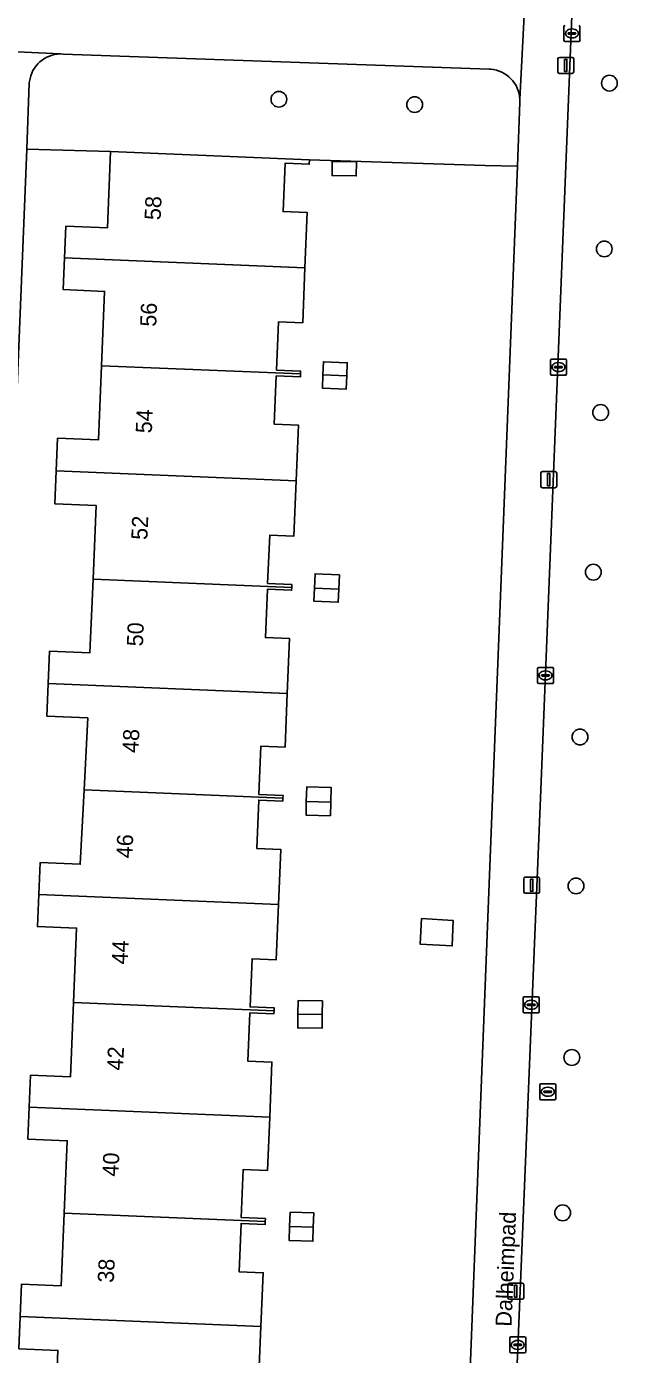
# Model space of a CAD drawing. Extents: x 160786 to 161429, y 386828 to 387485.
# Drawn here: x 161092.1 to 161129.1, y 386964.9 to 387047.4 of the extents above; entities that cross this region are included whole.
import ezdxf

# ---------------------------------------------------------------- set-up
doc = ezdxf.new("R2010")
doc.units = 0
for name, color, linetype in [('IMGEO_Boom', 7, 'Continuous'), ('IMGEO_Erf', 7, 'Continuous'), ('IMGEO_Groenvoorziening', 7, 'Continuous'), ('IMGEO_Kolk', 7, 'Continuous'), ('IMGEO_Lichtmast', 7, 'Continuous'), ('IMGEO_Openbare_ruimte_label', 7, 'Continuous'), ('IMGEO_Pand', 7, 'Continuous'), ('IMGEO_Pand_nummerreeks', 7, 'Continuous'), ('IMGEO_Rioolput', 7, 'Continuous'), ('IMGEO_Voetpad_open', 7, 'Continuous')]:
    doc.layers.add(name, color=color, linetype=linetype)

msp = doc.modelspace()

# ---------------------------------------------------------------- linework, layer by layer
at = {"layer": 'IMGEO_Boom'}
for centre in [(161128.309, 387043.866), (161107.785, 387042.864), (161116.214, 387042.533), (161127.99, 387033.572), (161127.766, 387023.417), (161127.313, 387013.503), (161126.485, 387003.27), (161126.234, 386994.026), (161125.975, 386983.377), (161125.408, 386973.732)]:
    msp.add_circle(centre, 0.489, dxfattribs=at)
at = {"layer": 'IMGEO_Erf'}
for points in [[(161091.805, 386969.307), (161094.274, 386969.205), (161094.46, 386973.708), (161094.645, 386978.211), (161092.204, 386978.311), (161092.285, 386980.29), (161092.367, 386982.27), (161094.843, 386982.168), (161095.033, 386986.787), (161095.224, 386991.406), (161092.789, 386991.506), (161092.87, 386993.49), (161092.952, 386995.477), (161095.453, 386995.374), (161095.688, 386999.985), (161095.916, 387004.462), (161093.376, 387004.569), (161093.461, 387006.59), (161093.545, 387008.608), (161096.05, 387008.502), (161096.242, 387013.075), (161096.435, 387017.648), (161093.867, 387017.756), (161093.952, 387019.788), (161094.037, 387021.819), (161096.573, 387021.712), (161096.767, 387026.322), (161096.961, 387030.937), (161094.394, 387031.045), (161094.477, 387033.018), (161094.559, 387034.989), (161097.135, 387034.881), (161097.334, 387039.615), (161092.128, 387039.776), (161090.524, 387000)], [(161119.475, 386959.244), (161121.076, 387000), (161122.596, 387038.706), (161120.603, 387038.743), (161109.681, 387039.096), (161109.67, 387038.826), (161108.171, 387038.889), (161108.045, 387035.892), (161109.545, 387035.829), (161109.403, 387032.398), (161109.261, 387028.986), (161107.762, 387029.048), (161107.637, 387026.051), (161109.136, 387025.989), (161109.129, 387025.809), (161109.122, 387025.629), (161107.623, 387025.691), (161107.498, 387022.694), (161108.997, 387022.632), (161108.853, 387019.169), (161108.711, 387015.74), (161107.212, 387015.802), (161107.087, 387012.805), (161108.586, 387012.743), (161108.579, 387012.563), (161108.572, 387012.383), (161107.073, 387012.445), (161106.948, 387009.448), (161108.447, 387009.386), (161108.305, 387005.973), (161108.167, 387002.648), (161106.668, 387002.71), (161106.543, 386999.713), (161108.042, 386999.651), (161108.035, 386999.471), (161108.027, 386999.291), (161106.529, 386999.353), (161106.404, 386996.356), (161107.902, 386996.294), (161107.76, 386992.871), (161107.618, 386989.446), (161106.119, 386989.508), (161105.994, 386986.511), (161107.493, 386986.449), (161107.486, 386986.269), (161107.479, 386986.089), (161105.98, 386986.151), (161105.855, 386983.154), (161107.354, 386983.092), (161107.212, 386979.67), (161107.074, 386976.367), (161105.575, 386976.429), (161105.451, 386973.432), (161106.949, 386973.37), (161106.942, 386973.19), (161106.935, 386973.01), (161105.436, 386973.072), (161105.311, 386970.075), (161106.811, 386970.013), (161106.672, 386966.677), (161106.528, 386963.209)], [(161093.874, 386960.552), (161094.065, 386965.19), (161091.639, 386965.29)]]:
    msp.add_lwpolyline(points, dxfattribs=at)
for points in [[(161111.099, 387038.992), (161112.604, 387038.973), (161112.593, 387038.108), (161111.088, 387038.127)], [(161110.484, 387024.931), (161110.518, 387025.751), (161110.552, 387026.573), (161112.034, 387026.511), (161112, 387025.69), (161111.966, 387024.87)], [(161109.952, 387011.708), (161109.99, 387012.504), (161110.032, 387013.404), (161111.546, 387013.333), (161111.504, 387012.442), (161111.466, 387011.636)], [(161109.488, 386999.258), (161109.51, 387000.174), (161111.03, 387000.138), (161111.008, 386999.221), (161110.988, 386998.385), (161109.468, 386998.421)], [(161116.547, 386990.415), (161116.641, 386992.002), (161118.605, 386991.889), (161118.545, 386990.303)], [(161108.955, 386985.211), (161108.964, 386986.061), (161108.972, 386986.905), (161110.485, 386986.891), (161110.477, 386986.047), (161110.469, 386985.196)], [(161108.419, 386972.018), (161108.446, 386972.884), (161108.474, 386973.77), (161109.948, 386973.724), (161109.92, 386972.837), (161109.893, 386971.972)]]:
    msp.add_lwpolyline(points, close=True, dxfattribs=at)
at = {"layer": 'IMGEO_Groenvoorziening'}
msp.add_lwpolyline([(161126.838, 387069.748), (161124.044, 387000), (161122.553, 386963.852)], dxfattribs=at)
msp.add_lwpolyline([(161122.596, 387038.706), (161122.753, 387042.692), (161122.751, 387042.869), (161122.734, 387043.045), (161122.701, 387043.218), (161122.652, 387043.388), (161122.589, 387043.553), (161122.511, 387043.712), (161122.419, 387043.863), (161122.314, 387044.005), (161122.196, 387044.137), (161122.068, 387044.258), (161121.929, 387044.367), (161121.781, 387044.464), (161121.625, 387044.547), (161121.462, 387044.615), (161121.293, 387044.669), (161121.121, 387044.707), (161120.946, 387044.73), (161120.849, 387044.736), (161094.392, 387045.669), (161094.218, 387045.676), (161094.044, 387045.667), (161093.871, 387045.642), (161093.702, 387045.602), (161093.536, 387045.548), (161093.377, 387045.478), (161093.224, 387045.395), (161093.079, 387045.298), (161092.943, 387045.189), (161092.817, 387045.068), (161092.703, 387044.937), (161092.601, 387044.795), (161092.512, 387044.645), (161092.437, 387044.488), (161092.376, 387044.325), (161092.33, 387044.157), (161092.3, 387043.986), (161092.287, 387043.86), (161092.128, 387039.776), (161097.334, 387039.615), (161109.681, 387039.096), (161120.603, 387038.743)], close=True, dxfattribs=at)
at = {"layer": 'IMGEO_Kolk'}
for p, q in [((161125.481, 387046.526), (161125.481, 387047.378)), ((161125.74, 387046.946), (161125.74, 387046.958)), ((161126.178, 387046.909), (161125.78, 387046.909)), ((161125.783, 387046.995), (161126.181, 387046.995)), ((161125.969, 387047.232), (161125.994, 387047.232)), ((161126.224, 387046.958), (161126.224, 387046.946)), ((161126.482, 387047.378), (161126.482, 387046.526)), ((161126.408, 387046.452), (161125.556, 387046.452)), ((161125.992, 387046.672), (161125.967, 387046.672)), ((161124.645, 387025.811), (161124.645, 387026.663)), ((161124.72, 387026.737), (161125.572, 387026.737)), ((161125.133, 387026.517), (161125.158, 387026.517)), ((161125.646, 387026.663), (161125.646, 387025.811)), ((161125.572, 387025.737), (161124.72, 387025.737)), ((161124.904, 387026.231), (161124.904, 387026.243)), ((161125.342, 387026.194), (161124.944, 387026.194)), ((161124.947, 387026.28), (161125.345, 387026.28)), ((161125.156, 387025.957), (161125.131, 387025.957)), ((161125.388, 387026.243), (161125.388, 387026.231)), ((161123.841, 387006.67), (161123.841, 387007.522)), ((161123.916, 387007.596), (161124.768, 387007.596)), ((161124.329, 387007.376), (161124.354, 387007.376)), ((161124.842, 387007.522), (161124.842, 387006.67)), ((161124.768, 387006.596), (161123.916, 387006.596)), ((161124.1, 387007.09), (161124.1, 387007.102)), ((161124.538, 387007.053), (161124.14, 387007.053)), ((161124.143, 387007.139), (161124.541, 387007.139)), ((161124.352, 387006.816), (161124.327, 387006.816)), ((161124.584, 387007.102), (161124.584, 387007.09)), ((161122.949, 386986.221), (161122.949, 386987.073)), ((161123.024, 386987.147), (161123.876, 386987.147)), ((161123.437, 386986.927), (161123.462, 386986.927)), ((161123.95, 386987.073), (161123.95, 386986.221)), ((161123.876, 386986.147), (161123.024, 386986.147)), ((161123.208, 386986.641), (161123.208, 386986.653)), ((161123.646, 386986.604), (161123.248, 386986.604)), ((161123.251, 386986.69), (161123.649, 386986.69)), ((161123.46, 386986.367), (161123.435, 386986.367)), ((161123.692, 386986.653), (161123.692, 386986.641)), ((161122.115, 386965.105), (161122.115, 386965.957)), ((161122.19, 386966.031), (161123.042, 386966.031)), ((161122.374, 386965.525), (161122.374, 386965.537)), ((161122.812, 386965.488), (161122.414, 386965.488)), ((161122.417, 386965.574), (161122.815, 386965.574)), ((161122.603, 386965.811), (161122.628, 386965.811)), ((161122.858, 386965.537), (161122.858, 386965.525)), ((161123.116, 386965.957), (161123.116, 386965.105)), ((161123.042, 386965.031), (161122.19, 386965.031)), ((161122.626, 386965.251), (161122.601, 386965.251))]:
    msp.add_line(p, q, dxfattribs=at)
for points in [[(161125.481, 387046.526), (161125.481, 387047.378)], [(161126.482, 387047.378), (161126.482, 387046.526)], [(161126.408, 387046.452), (161125.556, 387046.452)], [(161124.645, 387025.811), (161124.645, 387026.663)], [(161124.72, 387026.737), (161125.572, 387026.737)], [(161125.646, 387026.663), (161125.646, 387025.811)], [(161125.572, 387025.737), (161124.72, 387025.737)], [(161123.841, 387006.67), (161123.841, 387007.522)], [(161123.916, 387007.596), (161124.768, 387007.596)], [(161124.842, 387007.522), (161124.842, 387006.67)], [(161124.768, 387006.596), (161123.916, 387006.596)], [(161122.949, 386986.221), (161122.949, 386987.073)], [(161123.024, 386987.147), (161123.876, 386987.147)], [(161123.95, 386987.073), (161123.95, 386986.221)], [(161123.876, 386986.147), (161123.024, 386986.147)], [(161122.115, 386965.105), (161122.115, 386965.957)], [(161122.19, 386966.031), (161123.042, 386966.031)], [(161123.116, 386965.957), (161123.116, 386965.105)], [(161123.042, 386965.031), (161122.19, 386965.031)]]:
    msp.add_lwpolyline(points, dxfattribs=at)
for centre, radius, start, end in [((161125.558, 387047.376), 0.0765, 91.55205, 178.44795), ((161125.558, 387047.376), 0.0765, 91.55205, 178.44795), ((161125.78, 387046.955), 0.0403, 85.87752, 175.75265), ((161125.777, 387046.945), 0.0366, 178.93798, 274.71019), ((161126.181, 387046.952), 0.043, 264.86636, 352.45326), ((161126.185, 387046.957), 0.0386, 1.73085, 96.63898), ((161126.406, 387047.376), 0.0765, 1.55205, 88.44795), ((161126.406, 387047.376), 0.0765, 1.55205, 88.44795), ((161125.558, 387046.528), 0.0765, 181.55205, 268.44795), ((161125.558, 387046.528), 0.0765, 181.55205, 268.44795), ((161126.406, 387046.528), 0.0765, 271.55205, 358.44795), ((161126.406, 387046.528), 0.0765, 271.55205, 358.44795), ((161124.722, 387026.661), 0.0765, 91.55205, 178.44795), ((161124.722, 387026.661), 0.0765, 91.55205, 178.44795), ((161125.57, 387026.661), 0.0765, 1.55205, 88.44795), ((161125.57, 387026.661), 0.0765, 1.55205, 88.44795), ((161124.722, 387025.813), 0.0765, 181.55205, 268.44795), ((161124.722, 387025.813), 0.0765, 181.55205, 268.44795), ((161124.944, 387026.24), 0.0403, 85.87752, 175.75265), ((161124.941, 387026.23), 0.0366, 178.93798, 274.71019), ((161125.345, 387026.237), 0.043, 264.86636, 352.45326), ((161125.349, 387026.242), 0.0386, 1.73085, 96.63898), ((161125.57, 387025.813), 0.0765, 271.55205, 358.44795), ((161125.57, 387025.813), 0.0765, 271.55205, 358.44795), ((161123.918, 387007.52), 0.0765, 91.55205, 178.44795), ((161123.918, 387007.52), 0.0765, 91.55205, 178.44795), ((161124.766, 387007.52), 0.0765, 1.55205, 88.44795), ((161124.766, 387007.52), 0.0765, 1.55205, 88.44795), ((161123.918, 387006.672), 0.0765, 181.55205, 268.44795), ((161123.918, 387006.672), 0.0765, 181.55205, 268.44795), ((161124.14, 387007.099), 0.0403, 85.87752, 175.75265), ((161124.137, 387007.089), 0.0366, 178.93798, 274.71019), ((161124.541, 387007.096), 0.043, 264.86636, 352.45326), ((161124.545, 387007.101), 0.0386, 1.73085, 96.63898), ((161124.766, 387006.672), 0.0765, 271.55205, 358.44795), ((161124.766, 387006.672), 0.0765, 271.55205, 358.44795), ((161123.026, 386987.071), 0.0765, 91.55205, 178.44795), ((161123.026, 386987.071), 0.0765, 91.55205, 178.44795), ((161123.874, 386987.071), 0.0765, 1.55205, 88.44795), ((161123.874, 386987.071), 0.0765, 1.55205, 88.44795), ((161123.026, 386986.223), 0.0765, 181.55205, 268.44795), ((161123.026, 386986.223), 0.0765, 181.55205, 268.44795), ((161123.248, 386986.65), 0.0403, 85.87752, 175.75265), ((161123.245, 386986.64), 0.0366, 178.93798, 274.71019), ((161123.649, 386986.647), 0.043, 264.86636, 352.45326), ((161123.653, 386986.652), 0.0386, 1.73085, 96.63898), ((161123.874, 386986.223), 0.0765, 271.55205, 358.44795), ((161123.874, 386986.223), 0.0765, 271.55205, 358.44795), ((161122.192, 386965.955), 0.0765, 91.55205, 178.44795), ((161122.192, 386965.955), 0.0765, 91.55205, 178.44795), ((161122.414, 386965.534), 0.0403, 85.87752, 175.75265), ((161122.411, 386965.524), 0.0366, 178.93798, 274.71019), ((161122.815, 386965.531), 0.043, 264.86636, 352.45326), ((161122.819, 386965.536), 0.0386, 1.73085, 96.63898), ((161123.04, 386965.955), 0.0765, 1.55205, 88.44795), ((161123.04, 386965.955), 0.0765, 1.55205, 88.44795), ((161122.192, 386965.107), 0.0765, 181.55205, 268.44795), ((161122.192, 386965.107), 0.0765, 181.55205, 268.44795), ((161123.04, 386965.107), 0.0765, 271.55205, 358.44795), ((161123.04, 386965.107), 0.0765, 271.55205, 358.44795)]:
    msp.add_arc(centre, radius, start, end, dxfattribs=at)
for centre, major_axis, ratio, start_param, end_param in [((161125.968, 387046.952), (-0.387, 0.002), 0.722429, 4.712389, 7.853982), ((161125.993, 387046.952), (-0.39, 0.002), 0.717154, 1.570796, 4.712389), ((161125.132, 387026.237), (-0.387, 0.002), 0.722429, 4.712389, 7.853982), ((161125.157, 387026.237), (-0.39, 0.002), 0.717154, 1.570796, 4.712389), ((161124.328, 387007.096), (-0.387, 0.002), 0.722429, 4.712389, 7.853982), ((161124.353, 387007.096), (-0.39, 0.002), 0.717154, 1.570796, 4.712389), ((161123.436, 386986.647), (-0.387, 0.002), 0.722429, 4.712389, 7.853982), ((161123.461, 386986.647), (-0.39, 0.002), 0.717154, 1.570796, 4.712389), ((161122.602, 386965.531), (-0.387, 0.002), 0.722429, 4.712389, 7.853982), ((161122.627, 386965.531), (-0.39, 0.002), 0.717154, 1.570796, 4.712389)]:
    msp.add_ellipse(centre, major_axis=major_axis, ratio=ratio, start_param=start_param, end_param=end_param, dxfattribs=at)
at = {"layer": 'IMGEO_Lichtmast'}
for p, q in [((161125.099, 387044.566), (161125.099, 387045.366)), ((161125.099, 387045.366), (161125.099, 387044.566)), ((161125.199, 387045.466), (161125.989, 387045.466)), ((161125.989, 387045.466), (161125.199, 387045.466)), ((161126.089, 387045.366), (161126.089, 387044.566)), ((161126.089, 387044.566), (161126.089, 387045.366)), ((161125.989, 387044.466), (161125.199, 387044.466)), ((161125.199, 387044.466), (161125.989, 387044.466)), ((161124.147, 387019.75), (161124.937, 387019.75)), ((161124.937, 387019.75), (161124.147, 387019.75)), ((161124.047, 387018.85), (161124.047, 387019.65)), ((161124.047, 387019.65), (161124.047, 387018.85)), ((161125.037, 387019.65), (161125.037, 387018.85)), ((161125.037, 387018.85), (161125.037, 387019.65)), ((161124.937, 387018.75), (161124.147, 387018.75)), ((161124.147, 387018.75), (161124.937, 387018.75)), ((161122.987, 386993.669), (161122.987, 386994.469)), ((161122.987, 386994.469), (161122.987, 386993.669)), ((161123.087, 386994.569), (161123.877, 386994.569)), ((161123.877, 386994.569), (161123.087, 386994.569)), ((161123.977, 386994.469), (161123.977, 386993.669)), ((161123.977, 386993.669), (161123.977, 386994.469)), ((161123.877, 386993.569), (161123.087, 386993.569)), ((161123.087, 386993.569), (161123.877, 386993.569)), ((161121.996, 386968.465), (161121.996, 386969.265)), ((161121.996, 386969.265), (161121.996, 386968.465)), ((161122.096, 386969.365), (161122.886, 386969.365)), ((161122.886, 386969.365), (161122.096, 386969.365)), ((161122.986, 386969.265), (161122.986, 386968.465)), ((161122.986, 386968.465), (161122.986, 386969.265)), ((161122.886, 386968.365), (161122.096, 386968.365)), ((161122.096, 386968.365), (161122.886, 386968.365))]:
    msp.add_line(p, q, dxfattribs=at)
for points in [[(161125.519, 387045.341), (161125.669, 387045.341), (161125.669, 387044.591), (161125.519, 387044.591), (161125.519, 387045.341)], [(161124.467, 387019.625), (161124.617, 387019.625), (161124.617, 387018.875), (161124.467, 387018.875), (161124.467, 387019.625)], [(161123.407, 386994.444), (161123.557, 386994.444), (161123.557, 386993.694), (161123.407, 386993.694), (161123.407, 386994.444)], [(161122.416, 386969.24), (161122.566, 386969.24), (161122.566, 386968.49), (161122.416, 386968.49), (161122.416, 386969.24)]]:
    msp.add_lwpolyline(points, dxfattribs=at)
for centre, start, end in [((161125.199, 387045.366), 90, 180), ((161125.199, 387045.366), 90, 180), ((161125.989, 387045.366), 0, 90), ((161125.989, 387045.366), 360, 90), ((161125.199, 387044.566), 180, 270), ((161125.199, 387044.566), 180, 270), ((161125.989, 387044.566), 270, 0), ((161125.989, 387044.566), 270, 0), ((161124.147, 387019.65), 90, 180), ((161124.147, 387019.65), 90, 180), ((161124.937, 387019.65), 0, 90), ((161124.937, 387019.65), 360, 90), ((161124.147, 387018.85), 180, 270), ((161124.147, 387018.85), 180, 270), ((161124.937, 387018.85), 270, 0), ((161124.937, 387018.85), 270, 0), ((161123.087, 386994.469), 90, 180), ((161123.087, 386994.469), 90, 180), ((161123.877, 386994.469), 0, 90), ((161123.877, 386994.469), 360, 90), ((161123.087, 386993.669), 180, 270), ((161123.087, 386993.669), 180, 270), ((161123.877, 386993.669), 270, 0), ((161123.877, 386993.669), 270, 0), ((161122.096, 386969.265), 90, 180), ((161122.096, 386969.265), 90, 180), ((161122.886, 386969.265), 0, 90), ((161122.886, 386969.265), 360, 90), ((161122.096, 386968.465), 180, 270), ((161122.096, 386968.465), 180, 270), ((161122.886, 386968.465), 270, 0), ((161122.886, 386968.465), 270, 0)]:
    msp.add_arc(centre, 0.1, start, end, dxfattribs=at)
at = {"layer": 'IMGEO_Pand'}
for points in [[(161109.545, 387035.829), (161108.045, 387035.892), (161108.171, 387038.889), (161109.67, 387038.826), (161109.681, 387039.096), (161097.334, 387039.615), (161097.135, 387034.881), (161094.559, 387034.989), (161094.477, 387033.018), (161109.403, 387032.398)], [(161111.088, 387038.127), (161112.593, 387038.108), (161112.604, 387038.973), (161111.099, 387038.992)], [(161109.403, 387032.398), (161094.477, 387033.018), (161094.394, 387031.045), (161096.961, 387030.937), (161096.767, 387026.322), (161109.129, 387025.809), (161109.136, 387025.989), (161107.637, 387026.051), (161107.762, 387029.048), (161109.261, 387028.986)], [(161108.997, 387022.632), (161107.498, 387022.694), (161107.623, 387025.691), (161109.122, 387025.629), (161109.129, 387025.809), (161096.767, 387026.322), (161096.573, 387021.712), (161094.037, 387021.819), (161093.952, 387019.788), (161108.853, 387019.169)], [(161110.518, 387025.751), (161112, 387025.69), (161112.034, 387026.511), (161110.552, 387026.573)], [(161112, 387025.69), (161110.518, 387025.751), (161110.484, 387024.931), (161111.966, 387024.87)], [(161108.853, 387019.169), (161093.952, 387019.788), (161093.867, 387017.756), (161096.435, 387017.648), (161096.242, 387013.075), (161108.579, 387012.563), (161108.586, 387012.743), (161107.087, 387012.805), (161107.212, 387015.802), (161108.711, 387015.74)], [(161109.99, 387012.504), (161111.504, 387012.442), (161111.546, 387013.333), (161110.032, 387013.404)], [(161108.447, 387009.386), (161106.948, 387009.448), (161107.073, 387012.445), (161108.572, 387012.383), (161108.579, 387012.563), (161096.242, 387013.075), (161096.05, 387008.502), (161093.545, 387008.608), (161093.461, 387006.59), (161108.305, 387005.973)], [(161111.504, 387012.442), (161109.99, 387012.504), (161109.952, 387011.708), (161111.466, 387011.636)], [(161108.305, 387005.973), (161093.461, 387006.59), (161093.376, 387004.569), (161095.916, 387004.462), (161095.688, 386999.985), (161108.035, 386999.471), (161108.042, 386999.651), (161106.543, 386999.713), (161106.668, 387002.71), (161108.167, 387002.648)], [(161107.902, 386996.294), (161106.404, 386996.356), (161106.529, 386999.353), (161108.027, 386999.291), (161108.035, 386999.471), (161095.688, 386999.985), (161095.453, 386995.374), (161092.952, 386995.477), (161092.87, 386993.49), (161107.76, 386992.871)], [(161109.488, 386999.258), (161111.008, 386999.221), (161111.03, 387000.138), (161109.51, 387000.174)], [(161111.008, 386999.221), (161109.488, 386999.258), (161109.468, 386998.421), (161110.988, 386998.385)], [(161107.76, 386992.871), (161092.87, 386993.49), (161092.789, 386991.506), (161095.224, 386991.406), (161095.033, 386986.787), (161107.486, 386986.269), (161107.493, 386986.449), (161105.994, 386986.511), (161106.119, 386989.508), (161107.618, 386989.446)], [(161116.641, 386992.002), (161116.547, 386990.415), (161118.545, 386990.303), (161118.605, 386991.889)], [(161107.354, 386983.092), (161105.855, 386983.154), (161105.98, 386986.151), (161107.479, 386986.089), (161107.486, 386986.269), (161095.033, 386986.787), (161094.843, 386982.168), (161092.367, 386982.27), (161092.285, 386980.29), (161107.212, 386979.67)], [(161108.964, 386986.061), (161110.477, 386986.047), (161110.485, 386986.891), (161108.972, 386986.905)], [(161110.477, 386986.047), (161108.964, 386986.061), (161108.955, 386985.211), (161110.469, 386985.196)], [(161107.212, 386979.67), (161092.285, 386980.29), (161092.204, 386978.311), (161094.645, 386978.211), (161094.46, 386973.708), (161106.942, 386973.19), (161106.949, 386973.37), (161105.451, 386973.432), (161105.575, 386976.429), (161107.074, 386976.367)], [(161106.811, 386970.013), (161105.311, 386970.075), (161105.436, 386973.072), (161106.935, 386973.01), (161106.942, 386973.19), (161094.46, 386973.708), (161094.274, 386969.205), (161091.805, 386969.307), (161091.722, 386967.298), (161106.672, 386966.677)], [(161108.446, 386972.884), (161109.92, 386972.837), (161109.948, 386973.724), (161108.474, 386973.77)], [(161109.92, 386972.837), (161108.446, 386972.884), (161108.419, 386972.018), (161109.893, 386971.972)], [(161106.672, 386966.677), (161091.722, 386967.298), (161091.639, 386965.29), (161094.065, 386965.19), (161093.874, 386960.552), (161106.396, 386960.032), (161106.403, 386960.212), (161104.905, 386960.274), (161105.029, 386963.271), (161106.528, 386963.209)]]:
    msp.add_lwpolyline(points, close=True, dxfattribs=at)
at = {"layer": 'IMGEO_Rioolput'}
for p, q in [((161123.981, 386980.822), (161123.981, 386981.674)), ((161124.056, 386981.748), (161124.908, 386981.748)), ((161124.24, 386981.242), (161124.24, 386981.254)), ((161124.678, 386981.205), (161124.28, 386981.205)), ((161124.283, 386981.291), (161124.681, 386981.291)), ((161124.492, 386980.968), (161124.467, 386980.968)), ((161124.469, 386981.528), (161124.494, 386981.528)), ((161124.724, 386981.254), (161124.724, 386981.242)), ((161124.982, 386981.674), (161124.982, 386980.822)), ((161124.908, 386980.748), (161124.056, 386980.748))]:
    msp.add_line(p, q, dxfattribs=at)
for points in [[(161123.981, 386980.822), (161123.981, 386981.674)], [(161124.056, 386981.748), (161124.908, 386981.748)], [(161124.982, 386981.674), (161124.982, 386980.822)], [(161124.908, 386980.748), (161124.056, 386980.748)]]:
    msp.add_lwpolyline(points, dxfattribs=at)
for centre, radius, start, end in [((161124.058, 386981.672), 0.0765, 91.55205, 178.44795), ((161124.058, 386981.672), 0.0765, 91.55205, 178.44795), ((161124.28, 386981.251), 0.0403, 85.87752, 175.75265), ((161124.277, 386981.241), 0.0366, 178.93798, 274.71019), ((161124.681, 386981.248), 0.043, 264.86636, 352.45326), ((161124.685, 386981.253), 0.0386, 1.73085, 96.63898), ((161124.906, 386981.672), 0.0765, 1.55205, 88.44795), ((161124.906, 386981.672), 0.0765, 1.55205, 88.44795), ((161124.058, 386980.824), 0.0765, 181.55205, 268.44795), ((161124.058, 386980.824), 0.0765, 181.55205, 268.44795), ((161124.906, 386980.824), 0.0765, 271.55205, 358.44795), ((161124.906, 386980.824), 0.0765, 271.55205, 358.44795)]:
    msp.add_arc(centre, radius, start, end, dxfattribs=at)
for centre, major_axis, ratio, start_param, end_param in [((161124.468, 386981.248), (-0.387, 0.002), 0.722429, 4.712389, 7.853982), ((161124.493, 386981.248), (-0.39, 0.002), 0.717154, 1.570796, 4.712389)]:
    msp.add_ellipse(centre, major_axis=major_axis, ratio=ratio, start_param=start_param, end_param=end_param, dxfattribs=at)
at = {"layer": 'IMGEO_Voetpad_open'}
for points in [[(161128.864, 387071.378), (161129.056, 387074.52), (161124.099, 387074.719), (161123.098, 387049.797), (161123.092, 387049.703), (161122.751, 387042.869), (161122.753, 387042.692), (161122.596, 387038.706), (161121.076, 387000), (161119.475, 386959.244), (161118.604, 386937.102)], [(161120.37, 386911.783), (161120.564, 386917.225), (161120.797, 386923.755), (161120.97, 386928.628), (161121.017, 386929.934), (161121.473, 386936.897), (161122.253, 386956.657), (161122.251, 386956.693), (161122.549, 386963.816), (161122.553, 386963.852), (161124.044, 387000), (161126.838, 387069.748)], [(161086.592, 387046.04), (161094.218, 387045.676), (161094.392, 387045.669), (161120.849, 387044.736), (161120.946, 387044.73), (161121.121, 387044.707), (161121.293, 387044.669), (161121.462, 387044.615), (161121.625, 387044.547), (161121.781, 387044.464), (161121.929, 387044.367), (161122.068, 387044.258), (161122.196, 387044.137), (161122.314, 387044.005), (161122.419, 387043.863), (161122.511, 387043.712), (161122.589, 387043.553), (161122.652, 387043.388), (161122.701, 387043.218), (161122.734, 387043.045), (161122.751, 387042.869), (161123.092, 387049.703)], [(161090.524, 387000), (161092.128, 387039.776), (161092.287, 387043.86), (161092.3, 387043.986), (161092.33, 387044.157), (161092.376, 387044.325), (161092.437, 387044.488), (161092.512, 387044.645), (161092.601, 387044.795), (161092.703, 387044.937), (161092.817, 387045.068), (161092.943, 387045.189), (161093.079, 387045.298), (161093.224, 387045.395), (161093.377, 387045.478), (161093.536, 387045.548), (161093.702, 387045.602), (161093.871, 387045.642), (161094.044, 387045.667), (161094.218, 387045.676), (161086.592, 387046.04)]]:
    msp.add_lwpolyline(points, dxfattribs=at)

# ---------------------------------------------------------------- texts
at = {"layer": 'IMGEO_Openbare_ruimte_label'}
msp.add_text('Dalheimpad', height=1, rotation=87.7071, dxfattribs=at).set_placement((161122.23, 386966.651))
at = {"layer": 'IMGEO_Pand_nummerreeks'}
for s, rotation, p in [('58', 87.62244, (161100.439, 387035.349)), ('56', 87.62244, (161100.164, 387028.729)), ('54', 87.62244, (161099.889, 387022.113)), ('52', 87.62244, (161099.614, 387015.494)), ('50', 87.62244, (161099.339, 387008.884)), ('48', 87.62244, (161099.064, 387002.268)), ('46', 87.50211, (161098.679, 386995.727)), ('44', 87.50211, (161098.391, 386989.139)), ('42', 87.50211, (161098.104, 386982.548)), ('40', 87.50211, (161097.816, 386975.966)), ('38', 87.50211, (161097.529, 386969.378))]:
    msp.add_text(s, height=1, rotation=rotation, dxfattribs=at).set_placement(p)

doc.saveas('drawing.dxf')
